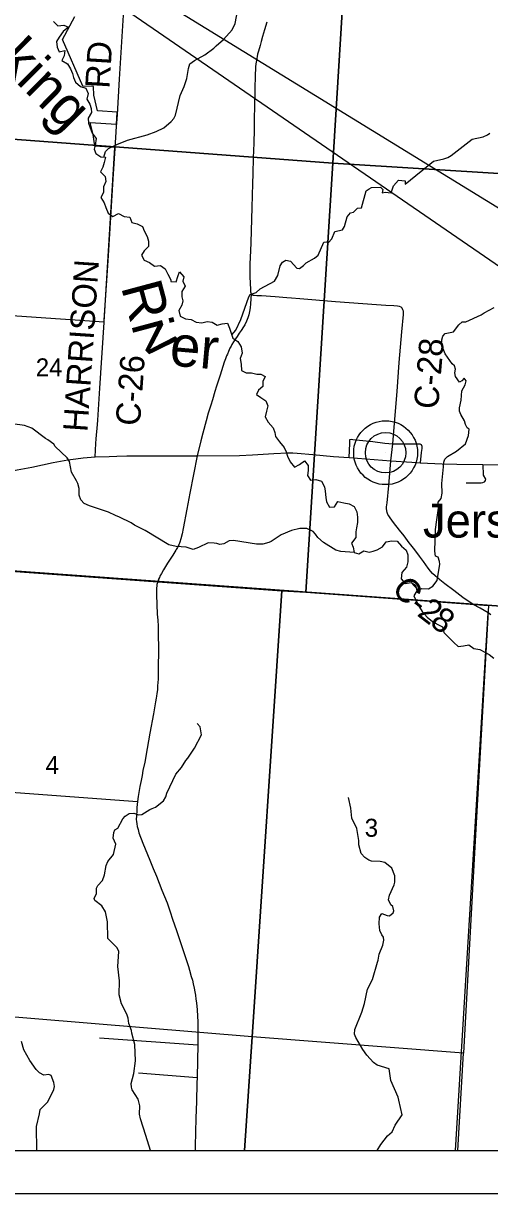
# Model space of a CAD drawing. Extents: x 0 to 91.3, y -0.7 to 22.
# Drawn here: x 6.125 to 7.212, y 14 to 16.725 of the extents above; entities that cross this region are included whole.
import ezdxf

# ---------------------------------------------------------------- set-up
doc = ezdxf.new("R2010")
doc.units = 0
for name, color, linetype in [('GM_X_City_Street', 7, 'Continuous'), ('GM_X_Corporation', 7, 'Continuous'), ('GM_X_County_Road', 7, 'Continuous'), ('GM_X_County_Road_Text', 7, 'Continuous'), ('GM_X_Major_River', 7, 'Continuous'), ('GM_X_Major_River_Text', 7, 'Continuous'), ('GM_X_Minor_River', 7, 'Continuous'), ('GM_X_Section_Text', 7, 'Continuous'), ('GM_X_Township_Road', 7, 'Continuous'), ('GM_X_Unincorporated', 7, 'Continuous'), ('GM_X_Unincorporated_Location', 7, 'Continuous'), ('GM_X_Unincorporated_Text', 7, 'Continuous'), ('SH_Data', 7, 'Continuous'), ('SH_Text', 7, 'Continuous')]:
    doc.layers.add(name, color=color, linetype=linetype)

msp = doc.modelspace()

# ---------------------------------------------------------------- linework, layer by layer
at = {"layer": 'GM_X_City_Street'}
for p, q in [((7.1321, 14.1), (7.2079, 15.352)), ((5.6815, 14.9665), (6.3908, 14.9126)), ((6.3026, 14.3628), (6.5313, 14.3463)), ((6.3934, 14.2814), (6.5298, 14.2704))]:
    msp.add_line(p, q, dxfattribs=at)
at = {"layer": 'GM_X_Corporation'}
for points in [[(4.8242, 18.6326), (4.7833, 18.1361), (4.7799, 18.0944), (4.7688, 17.9561), (4.7562, 17.8002), (4.7391, 17.5254), (4.7381, 17.5094), (4.7369, 17.4842), (4.7039, 16.921), (4.6966, 16.7952), (4.624, 15.5538), (4.6241, 15.5494), (4.6027, 15.2253), (4.5901, 15.0403), (4.5616, 14.5843), (4.5361, 14.2234), (4.5273, 14.1), (8.9, 14.1), (8.9, 20.9)], [(4.8242, 18.6326), (4.7833, 18.1361), (4.7799, 18.0944), (4.7688, 17.9561), (4.7562, 17.8002), (4.7391, 17.5254), (4.7381, 17.5094), (4.7369, 17.4842), (4.7039, 16.921), (4.6966, 16.7952), (4.624, 15.5538), (4.6241, 15.5494), (5.2553, 15.5081), (5.7371, 15.476), (6.438, 15.425), (7.1732, 15.3725), (7.6407, 15.3389), (8.8181, 15.2648), (8.9, 15.2596), (8.9, 20.4953)], [(5.8036, 16.0651), (6.313, 16.0296), (6.3385, 16.4356), (6.2918, 16.4387), (6.2873, 16.4662), (6.2807, 16.4943), (6.3421, 16.49), (6.3438, 16.5179), (6.2974, 16.521), (6.2893, 16.5576), (6.2884, 16.5776), (6.2639, 16.5784), (6.2162, 16.6875), (6.2451, 16.7407)]]:
    msp.add_lwpolyline(points, dxfattribs=at)
for points in [[(5.8879, 17.4801), (6.9092, 17.4181), (6.8465, 16.3992), (5.8298, 16.4755)], [(6.9092, 17.4181), (7.9172, 17.3589), (7.8571, 16.3365), (6.8465, 16.3992)], [(5.8298, 16.4755), (6.8465, 16.3992), (6.7835, 15.4003), (6.727, 15.4038), (5.7634, 15.4732)], [(6.8465, 16.3992), (7.8571, 16.3365), (7.7907, 15.3289), (7.2092, 15.3695), (6.7835, 15.4003)], [(4.5273, 14.1), (8.9, 14.1), (8.9, 15.2596), (8.8181, 15.2648), (7.6407, 15.3389), (7.1732, 15.3725), (6.438, 15.425), (5.7371, 15.476), (5.2553, 15.5081), (4.6241, 15.5494), (4.6027, 15.2253), (4.5901, 15.0403), (4.5616, 14.5843), (4.5361, 14.2234)], [(4.5286, 14.1), (8.9, 14.1), (8.9, 15.2593), (7.6407, 15.3389), (7.1732, 15.3725), (5.7332, 15.4763), (5.3098, 15.5058), (4.9415, 15.5315), (4.9055, 15.5345), (4.624, 15.5538)], [(5.7168, 15.4767), (5.7634, 15.4732), (6.727, 15.4038), (6.6586, 14.3652), (5.6446, 14.4487)], [(6.727, 15.4038), (6.7835, 15.4003), (7.2092, 15.3695), (7.1789, 14.8356), (7.1508, 14.3266), (6.6586, 14.3652)], [(5.6181, 14.1), (6.6403, 14.1), (6.6586, 14.3652), (5.6446, 14.4487)], [(6.6403, 14.1), (7.1375, 14.1), (7.1508, 14.3266), (6.6586, 14.3652)]]:
    msp.add_lwpolyline(points, close=True, dxfattribs=at)
at = {"layer": 'GM_X_County_Road'}
msp.add_line((6.3428, 16.4928), (6.3441, 16.5128), dxfattribs=at)
for points in [[(6.3441, 16.5128), (6.3491, 16.5947), (6.3656, 16.8567), (6.3814, 17.0978), (6.3885, 17.2334), (6.4013, 17.4498)], [(6.6924, 16.7276), (6.6872, 16.7094), (6.6824, 16.6941), (6.6792, 16.6827), (6.6765, 16.6735), (6.6727, 16.6603), (6.6707, 16.6529), (6.6698, 16.648), (6.6688, 16.6431), (6.6681, 16.6385), (6.6673, 16.6343), (6.6668, 16.6304), (6.6662, 16.6235), (6.6657, 16.6159), (6.6654, 16.6091), (6.6646, 16.5672), (6.6639, 16.531), (6.6632, 16.5031), (6.6626, 16.4778), (6.6625, 16.4456), (6.6609, 16.4117), (6.6597, 16.3745), (6.6589, 16.3516), (6.6575, 16.2961), (6.6553, 16.2148), (6.6542, 16.195), (6.6529, 16.1648), (6.6528, 16.1528), (6.653, 16.1416), (6.653, 16.1372), (6.6531, 16.1314), (6.6537, 16.1233), (6.6538, 16.1172), (6.6541, 16.1072), (6.6546, 16.0996), (6.6558, 16.0949), (6.6551, 16.0836), (6.6546, 16.0717), (6.6538, 16.0628), (6.6524, 16.054), (6.6506, 16.0464), (6.6482, 16.039), (6.6451, 16.0315), (6.6411, 16.0232), (6.6382, 16.0185), (6.6323, 16.0095), (6.6282, 16.0033), (6.6231, 15.996), (6.6194, 15.9904), (6.6146, 15.9833), (6.611, 15.9768), (6.609, 15.9734), (6.6064, 15.9685), (6.6028, 15.9606), (6.6004, 15.9549), (6.5986, 15.9509), (6.5959, 15.9436), (6.5931, 15.9359), (6.5896, 15.9256), (6.5833, 15.9056), (6.5796, 15.8937), (6.5751, 15.88), (6.5714, 15.8679), (6.5655, 15.8485), (6.5616, 15.8356), (6.5559, 15.817), (6.5512, 15.7995), (6.5434, 15.7709), (6.5387, 15.7527), (6.5301, 15.718)], [(6.339, 16.4332), (6.3424, 16.4858), (6.3428, 16.4928)], [(6.3136, 16.034), (6.3236, 16.184), (6.3345, 16.3626), (6.339, 16.4332)], [(6.9813, 15.7065), (6.9858, 15.7459), (6.99, 15.7942), (6.996, 15.868), (7.0012, 15.9355), (7.0071, 16.0065), (7.0111, 16.0467), (7.0108, 16.0543), (7.0097, 16.0579), (7.0078, 16.0616), (7.0053, 16.0639), (7.0018, 16.0653), (6.997, 16.066), (6.9881, 16.0668), (6.9701, 16.0678), (6.948, 16.0694), (6.8528, 16.0764), (6.7694, 16.0831), (6.7496, 16.0848), (6.7392, 16.0859), (6.7115, 16.088), (6.6798, 16.0901), (6.6689, 16.0907), (6.6631, 16.0912), (6.6608, 16.0915), (6.6583, 16.0926), (6.6558, 16.0949)], [(6.2926, 15.7156), (6.2937, 15.7468), (6.2945, 15.7577), (6.2975, 15.7905), (6.2984, 15.8006), (6.3036, 15.8756), (6.3132, 16.028), (6.3136, 16.034)], [(6.5301, 15.718), (6.6286, 15.7188), (6.6594, 15.7203), (6.7086, 15.7233), (6.7409, 15.7246), (6.7529, 15.7247), (6.7629, 15.724), (6.7998, 15.721), (6.8477, 15.7166), (6.8843, 15.7136), (6.9813, 15.7065), (7.0305, 15.703), (7.0496, 15.7018), (7.1008, 15.6994), (7.1352, 15.6986), (7.1957, 15.6977), (7.2485, 15.6967)], [(5.9032, 15.6474), (6.0541, 15.6743), (6.1102, 15.6849), (6.1444, 15.6918), (6.1946, 15.7021), (6.2285, 15.7083), (6.2474, 15.7112), (6.2642, 15.7133), (6.2926, 15.7156)], [(6.2926, 15.7156), (6.3247, 15.7165), (6.3427, 15.7168), (6.3664, 15.7175), (6.4076, 15.7179), (6.5301, 15.718)], [(6.5301, 15.718), (6.5133, 15.6312), (6.5106, 15.6184), (6.506, 15.5935), (6.4978, 15.549), (6.4951, 15.5362), (6.492, 15.5248), (6.4894, 15.5165), (6.487, 15.5107), (6.4859, 15.508), (6.4842, 15.5047), (6.4825, 15.5019), (6.4815, 15.4998), (6.4804, 15.4982), (6.473, 15.4866), (6.4613, 15.4679), (6.4559, 15.4599), (6.4513, 15.4522), (6.4466, 15.4438), (6.443, 15.4373), (6.4419, 15.4349), (6.4403, 15.4308), (6.44, 15.4299)], [(7.1734, 15.3719), (7.1492, 15.3882), (7.1285, 15.4039), (7.1073, 15.4199), (7.0957, 15.4293), (7.0845, 15.4383), (7.0783, 15.4441), (7.0739, 15.449), (7.0685, 15.4561), (7.0573, 15.4719), (7.0484, 15.4839), (7.0375, 15.4991), (7.0282, 15.5107), (7.0245, 15.5155), (7.0124, 15.5314), (7.0019, 15.5451), (6.988, 15.5627), (6.98, 15.5735), (6.9766, 15.5779), (6.9747, 15.5816), (6.9731, 15.5862), (6.9721, 15.59), (6.9716, 15.5955), (6.9717, 15.5993), (6.9727, 15.6083), (6.9771, 15.649), (6.9813, 15.7065)], [(6.44, 15.4299), (6.4382, 15.4245), (6.4364, 15.4179), (6.4357, 15.4144), (6.4354, 15.4103), (6.4351, 15.4036), (6.435, 15.3938), (6.4371, 15.3488), (6.4383, 15.335), (6.4389, 15.3214), (6.439, 15.3034), (6.4396, 15.2681), (6.4392, 15.2214), (6.439, 15.1981), (6.4379, 15.1821), (6.4373, 15.1733), (6.4362, 15.1648), (6.4352, 15.1583), (6.4343, 15.1533), (6.4331, 15.1452), (6.4321, 15.1404), (6.4284, 15.1173), (6.4199, 15.0718), (6.4139, 15.0367), (6.4078, 15.0045), (6.4037, 14.9853), (6.4016, 14.9736), (6.3992, 14.9618), (6.3965, 14.9476), (6.394, 14.934), (6.3924, 14.9243), (6.3908, 14.9126), (6.3895, 14.8991), (6.3891, 14.8922), (6.3885, 14.8794), (6.3882, 14.8708), (6.3886, 14.8663), (6.3893, 14.8606), (6.3906, 14.855), (6.3923, 14.8476), (6.3945, 14.8404), (6.4037, 14.816), (6.4201, 14.7763), (6.4278, 14.7568), (6.435, 14.7391), (6.4477, 14.7067), (6.4598, 14.6774), (6.4673, 14.6557), (6.4728, 14.6393), (6.4819, 14.6128), (6.49, 14.5894), (6.4952, 14.573), (6.5006, 14.5568), (6.5096, 14.5286), (6.5122, 14.52), (6.5163, 14.5054), (6.5189, 14.4966), (6.5211, 14.4881), (6.5232, 14.4782), (6.5249, 14.4699), (6.5263, 14.4622), (6.5273, 14.4531), (6.5283, 14.444), (6.53, 14.4279), (6.5315, 14.3994), (6.5315, 14.3808), (6.5317, 14.3532), (6.5313, 14.3463), (6.531, 14.3098), (6.5298, 14.2704), (6.5296, 14.257), (6.5282, 14.2144), (6.527, 14.1757), (6.5256, 14.1108), (6.5254, 14.1)], [(7.2144, 15.3476), (7.2079, 15.352), (7.1896, 15.3628), (7.1734, 15.3719)]]:
    msp.add_lwpolyline(points, dxfattribs=at)
at = {"layer": 'GM_X_Major_River'}
for points in [[(6.1956, 16.7293), (6.2055, 16.7194), (6.2191, 16.7205), (6.2301, 16.7159), (6.2179, 16.7061), (6.2088, 16.6928), (6.2019, 16.6826), (6.2034, 16.669), (6.2086, 16.6587), (6.2215, 16.6617), (6.2204, 16.6492), (6.215, 16.6382), (6.2275, 16.6302), (6.235, 16.6188), (6.2392, 16.6082), (6.2422, 16.5987), (6.2467, 16.5877), (6.2584, 16.5778), (6.2705, 16.5743), (6.2761, 16.5614), (6.2731, 16.5481), (6.2798, 16.5363), (6.2832, 16.5268), (6.2836, 16.5174), (6.2759, 16.5041), (6.277, 16.4924), (6.2808, 16.4814), (6.2856, 16.4692), (6.2947, 16.4566), (6.292, 16.4415), (6.2901, 16.4316), (6.2938, 16.4221), (6.3059, 16.4141), (6.3165, 16.413), (6.3134, 16.4008), (6.3104, 16.3898), (6.305, 16.3793), (6.316, 16.3686), (6.3171, 16.3568), (6.3117, 16.344), (6.3117, 16.3307), (6.3052, 16.3193), (6.3131, 16.3068), (6.3172, 16.2958), (6.3225, 16.2825), (6.3334, 16.2752), (6.3467, 16.2824)], [(6.3467, 16.2824), (6.36, 16.2751), (6.3729, 16.2736), (6.3781, 16.2614), (6.3902, 16.2583), (6.4023, 16.2515), (6.4065, 16.242), (6.4132, 16.2287), (6.4166, 16.218), (6.4166, 16.2055), (6.4063, 16.1953), (6.4002, 16.1851), (6.4066, 16.1737), (6.4187, 16.168), (6.4308, 16.1592), (6.4448, 16.1611), (6.4554, 16.1534), (6.4618, 16.1409), (6.469, 16.128)], [(6.469, 16.128), (6.4686, 16.1238), (6.4811, 16.123), (6.4853, 16.1355), (6.4891, 16.1465), (6.4993, 16.1347), (6.4963, 16.1244), (6.5023, 16.1127), (6.4943, 16.1002), (6.4942, 16.0881), (6.4965, 16.0786), (6.4945, 16.0683), (6.4873, 16.0559), (6.4903, 16.0429), (6.5031, 16.0365), (6.516, 16.0356), (6.5274, 16.0288), (6.5406, 16.0276), (6.5531, 16.0306), (6.5653, 16.029), (6.5766, 16.0218), (6.5884, 16.0255), (6.6005, 16.0266), (6.6058, 16.0152), (6.6095, 16.0038), (6.6133, 15.9917), (6.625, 15.9837), (6.6325, 15.9719), (6.6348, 15.9571), (6.6302, 15.9442), (6.6324, 15.9309), (6.6335, 15.9169), (6.6441, 15.9108), (6.6569, 15.9111), (6.6691, 15.908), (6.6785, 15.9076), (6.6884, 15.9026), (6.683, 15.8909), (6.6834, 15.8791), (6.6731, 15.8708), (6.6681, 15.8603), (6.6787, 15.8534), (6.6901, 15.8461), (6.6946, 15.8344), (6.6919, 15.8222), (6.6888, 15.8086), (6.6952, 15.7961), (6.7069, 15.7831), (6.711, 15.7721), (6.7129, 15.7626), (6.7219, 15.7505), (6.7332, 15.7375), (6.7374, 15.7273), (6.7404, 15.717), (6.7471, 15.7041), (6.757, 15.6912), (6.7684, 15.698), (6.7801, 15.7063), (6.7888, 15.6956), (6.7888, 15.6835), (6.7872, 15.6717), (6.7944, 15.6615), (6.8065, 15.6629), (6.8198, 15.6587), (6.8265, 15.6454), (6.828, 15.6352), (6.8302, 15.6211), (6.8313, 15.6105), (6.8381, 15.5984), (6.8499, 15.5994), (6.8579, 15.6115), (6.8715, 15.6085), (6.8844, 15.6058), (6.8961, 15.5996), (6.9021, 15.5875), (6.904, 15.575), (6.9036, 15.5628), (6.9012, 15.5503), (6.8997, 15.5409), (6.8996, 15.528), (6.8901, 15.5147), (6.8939, 15.5052), (6.8961, 15.4927), (6.9071, 15.4893), (6.9185, 15.4968), (6.9306, 15.4933), (6.9401, 15.4956), (6.9496, 15.499), (6.9617, 15.5057), (6.9709, 15.5178), (6.9834, 15.5201), (6.9963, 15.5193), (7.0061, 15.5078), (7.017, 15.4979), (7.0212, 15.4873), (7.0211, 15.4714), (7.0177, 15.4589), (7.0074, 15.4464), (7.0058, 15.4313), (7.0152, 15.4206), (7.0289, 15.4228)], [(7.0289, 15.4228), (7.0387, 15.4167), (7.0421, 15.4038), (7.0352, 15.3921), (7.0416, 15.3788), (7.048, 15.3651), (7.0548, 15.3556), (7.0661, 15.3423), (7.0786, 15.3324), (7.0907, 15.3251), (7.102, 15.3194), (7.105, 15.3065), (7.1175, 15.2943), (7.1281, 15.2833), (7.1383, 15.2738), (7.1508, 15.2753), (7.1629, 15.2775), (7.175, 15.2691), (7.1887, 15.2668), (7.2008, 15.261), (7.2106, 15.2553), (7.2212, 15.2469)]]:
    msp.add_lwpolyline(points, dxfattribs=at)
at = {"layer": 'GM_X_Minor_River'}
for points in [[(6.3122, 16.4134), (6.3165, 16.4266), (6.3237, 16.4338), (6.3431, 16.4431), (6.3674, 16.4525), (6.4134, 16.4655), (6.4346, 16.4729), (6.4525, 16.4819), (6.4696, 16.4962), (6.4754, 16.5034), (6.4792, 16.5113), (6.4908, 16.5568), (6.4997, 16.578), (6.5062, 16.5965), (6.5098, 16.6196), (6.5132, 16.6302), (6.5239, 16.6385), (6.5478, 16.6513), (6.5688, 16.6674), (6.5745, 16.6727), (6.5916, 16.687), (6.6115, 16.7096), (6.6188, 16.7244), (6.625, 16.7574)], [(6.6108, 15.9996), (6.6201, 16.0103), (6.632, 16.0349), (6.6505, 16.0882), (6.6539, 16.0932), (6.6672, 16.0984), (6.6771, 16.1063), (6.7106, 16.1247), (6.7182, 16.1375), (6.7237, 16.1599), (6.7286, 16.1689), (6.737, 16.1738), (6.7472, 16.1711), (6.7623, 16.1547), (6.7687, 16.1539), (6.7775, 16.1611), (6.784, 16.1671), (6.8038, 16.1784), (6.8117, 16.1847), (6.8256, 16.2154), (6.8309, 16.2161), (6.8358, 16.2142), (6.8442, 16.2229), (6.8511, 16.2399), (6.8686, 16.2443), (6.8732, 16.2515), (6.8797, 16.2742), (6.8877, 16.284), (6.8942, 16.2855), (6.9034, 16.2946), (6.9132, 16.2953), (6.924, 16.335), (6.9309, 16.3399), (6.9362, 16.3425), (6.9571, 16.3432), (6.9624, 16.3378), (6.9616, 16.3302), (6.968, 16.3321), (6.982, 16.3301), (6.9878, 16.3464), (6.9996, 16.36), (7.0148, 16.358), (7.0151, 16.3504), (7.0806, 16.4039), (7.1053, 16.4094), (7.114, 16.4128), (7.1224, 16.4169), (7.1708, 16.4549), (7.1966, 16.4608), (7.2068, 16.4649), (7.2122, 16.4691)], [(7.0289, 15.4228), (7.0451, 15.4052), (7.0534, 15.4086), (7.069, 15.4085), (7.0796, 15.4141), (7.0896, 15.4277), (7.0955, 15.4656), (7.0951, 15.4721), (7.0914, 15.4816), (7.0857, 15.4843), (7.0839, 15.496), (7.0853, 15.5464), (7.0888, 15.5688), (7.0928, 15.5957), (7.0921, 15.6101), (7.099, 15.6188), (7.1009, 15.6309), (7.1003, 15.6537), (7.1039, 15.6923), (7.1051, 15.7033), (7.1071, 15.7097), (7.1132, 15.7165), (7.1348, 15.7289), (7.1554, 15.7455), (7.1623, 15.7655), (7.1643, 15.7803), (7.1594, 15.7834), (7.1557, 15.7906), (7.1534, 15.799), (7.1448, 15.8138), (7.1418, 15.8218), (7.1411, 15.8294), (7.1457, 15.8472), (7.1466, 15.8695), (7.155, 15.8831), (7.1566, 15.8926), (7.1521, 15.8983), (7.1471, 15.8923), (7.1411, 15.8897), (7.1324, 15.9022), (7.1309, 15.9113), (7.1325, 15.92), (7.1299, 15.9276), (7.1242, 15.9322), (7.1081, 15.9555), (7.0998, 15.9764), (7.1003, 15.9877), (7.1026, 15.9968), (7.1079, 16.0025), (7.1277, 16.0065), (7.1399, 16.0228), (7.1475, 16.0299), (7.1559, 16.0299), (7.192, 16.0463), (7.1988, 16.0509), (7.2224, 16.0636)], [(6.8961, 15.4927), (6.8651, 15.4947), (6.853, 15.4982), (6.8243, 15.5158), (6.8111, 15.5276), (6.8055, 15.5356), (6.8002, 15.5417), (6.7858, 15.5486), (6.7695, 15.5487), (6.7498, 15.5439), (6.7255, 15.5342), (6.7026, 15.518), (6.6969, 15.5158), (6.6829, 15.5121), (6.6681, 15.5125), (6.6151, 15.5204), (6.6048, 15.5197), (6.5923, 15.5133), (6.5832, 15.5115), (6.576, 15.5134), (6.5699, 15.5146), (6.5555, 15.5155), (6.5331, 15.5042), (6.5205, 15.5001), (6.5043, 15.5055), (6.4808, 15.5068), (6.4641, 15.5107), (6.4086, 15.5436), (6.384, 15.5563), (6.3761, 15.562), (6.3488, 15.5751), (6.3401, 15.5789), (6.3231, 15.5866), (6.2792, 15.6013), (6.2664, 15.607), (6.2592, 15.6151), (6.2551, 15.6261), (6.2548, 15.642), (6.2522, 15.6534), (6.2492, 15.6595), (6.2372, 15.6796), (6.2324, 15.7043), (6.2272, 15.7131), (6.1989, 15.7398), (6.1959, 15.7451), (6.1819, 15.7554), (6.1766, 15.7585), (6.1445, 15.7822), (6.1279, 15.7884), (6.0998, 15.7923)], [(6.4216, 14.1), (6.4105, 14.1355), (6.3982, 14.1739), (6.396, 14.1849), (6.3961, 14.2046), (6.3928, 14.2201), (6.3789, 14.2418), (6.3767, 14.2479), (6.3763, 14.2563), (6.3825, 14.2797), (6.3861, 14.3093), (6.3848, 14.3468), (6.3781, 14.3734), (6.3774, 14.3795), (6.371, 14.3958), (6.3692, 14.4083), (6.3659, 14.4178), (6.3535, 14.4422), (6.3479, 14.463), (6.3492, 14.4953), (6.3453, 14.5287), (6.3477, 14.5639), (6.344, 14.5726), (6.3221, 14.594), (6.3212, 14.6327), (6.3168, 14.6562), (6.3081, 14.6703), (6.2919, 14.6825), (6.2897, 14.6875), (6.2954, 14.6988), (6.2955, 14.7113), (6.2982, 14.717), (6.3092, 14.7294), (6.3142, 14.7423), (6.3178, 14.7639), (6.322, 14.7733), (6.3353, 14.7892), (6.3408, 14.8134), (6.3344, 14.8279), (6.3356, 14.8407), (6.3379, 14.8468), (6.3448, 14.8505), (6.357, 14.8728), (6.362, 14.8785), (6.3715, 14.8849), (6.3825, 14.8856), (6.3935, 14.8821), (6.4011, 14.8828), (6.4197, 14.8945), (6.425, 14.8963), (6.433, 14.9001), (6.4513, 14.9147), (6.457, 14.9242), (6.459, 14.9325), (6.4801, 14.9764), (6.4938, 14.9918), (6.5038, 15.0085), (6.508, 15.0137), (6.5236, 15.0375), (6.5401, 15.0681), (6.5368, 15.0867), (6.53, 15.0944)], [(6.9676, 14.7706), (6.9562, 14.7734), (6.9365, 14.7742), (6.9301, 14.7762), (6.9206, 14.7823), (6.9124, 14.7918), (6.9072, 14.8123), (6.9065, 14.8222), (6.9025, 14.8503), (6.8908, 14.8742), (6.8879, 14.8977), (6.8824, 14.922)], [(6.9499, 14.1), (6.9582, 14.1144), (6.9739, 14.1348), (6.9842, 14.1435), (6.9918, 14.1597), (7.0079, 14.1835), (7.0001, 14.2173), (6.9983, 14.2249), (6.9814, 14.2637), (6.9774, 14.2906), (6.9494, 14.2991), (6.9411, 14.3056), (6.9256, 14.3224), (6.9162, 14.3353), (6.9001, 14.3635), (6.8971, 14.3711), (6.8975, 14.3817), (6.9137, 14.4222), (6.9203, 14.4426), (6.9269, 14.4759), (6.9388, 14.4986), (6.9504, 14.5387), (6.9519, 14.5436), (6.9539, 14.5573), (6.9631, 14.5788), (6.9654, 14.5898), (6.964, 14.597), (6.9602, 14.6023), (6.9561, 14.6126), (6.9539, 14.6285), (6.9547, 14.6437), (6.9601, 14.6524), (6.973, 14.6474), (6.9783, 14.647), (6.9866, 14.6534), (6.9882, 14.6587), (6.986, 14.6685), (6.9811, 14.6727), (6.9758, 14.6841), (6.9782, 14.6951), (6.9893, 14.7186), (6.9905, 14.7254), (6.9905, 14.7337), (6.9905, 14.7402), (6.9838, 14.758), (6.9676, 14.7706)], [(6.1566, 14.1), (6.1559, 14.156), (6.1629, 14.1855), (6.1641, 14.1957), (6.182, 14.2138), (6.1962, 14.2422), (6.1973, 14.2497), (6.1963, 14.2585), (6.1899, 14.2748), (6.1846, 14.2771), (6.1725, 14.276), (6.1626, 14.2814), (6.1547, 14.289), (6.1397, 14.3096), (6.1258, 14.3351), (6.121, 14.3545)]]:
    msp.add_lwpolyline(points, dxfattribs=at)
at = {"layer": 'GM_X_Township_Road'}
for points in [[(6.8843, 15.7136), (6.8856, 15.7464), (6.8855, 15.7526), (6.8861, 15.756), (6.8891, 15.7563), (6.8925, 15.756), (6.9396, 15.751), (6.9674, 15.7475), (6.9858, 15.7459), (6.9953, 15.7459), (7.0035, 15.7459), (7.0375, 15.7456), (7.049, 15.7454), (7.0524, 15.7442), (7.0539, 15.7403), (7.0539, 15.7352), (7.0523, 15.7255), (7.0496, 15.7018)], [(7.1957, 15.6977), (7.1964, 15.6729), (7.2017, 15.6636), (7.201, 15.6605), (7.1999, 15.6581), (7.1989, 15.6568), (7.1968, 15.6557), (7.1947, 15.6549), (7.1918, 15.6544), (7.18, 15.6539), (7.17, 15.6542), (7.1566, 15.6539)]]:
    msp.add_lwpolyline(points, dxfattribs=at)
at = {"layer": 'GM_X_Unincorporated'}
for radius in [0.0744, 0.0472]:
    msp.add_circle((6.9692, 15.7251), radius, dxfattribs=at)
at = {"layer": 'GM_X_Unincorporated_Location'}
msp.add_line((6.9692, 15.7251), (6.9692, 15.7251), dxfattribs=at)
at = {"layer": 'SH_Data'}
for p, q in [((2.1, 14.1), (8.9, 14.1)), ((2, 14), (9, 14))]:
    msp.add_line(p, q, dxfattribs=at)
at = {"layer": 'SH_Text'}
msp.add_lwpolyline([(9.2012, 14.8079), (5.3743, 17.4358), (9.2012, 15.0876)], close=True, dxfattribs=at)

# ---------------------------------------------------------------- texts
at = {"layer": 'GM_X_County_Road_Text'}
for s, height, rotation, p in [('RD', 0.05682, 86.5523, (6.3257, 16.5721)), ('HARRISON', 0.05682, 86.1242, (6.2741, 15.7725)), ('C-28', 0.05682, 85.2082, (7.0914, 15.8253)), ('C-26', 0.05682, 85.8892, (6.3965, 15.7864)), ('C', 0.0568, 308.3227, (6.9819, 15.4089)), ('-', 0.0568, 322.4898, (7.0218, 15.3615)), ('2', 0.0568, 322.4244, (7.0403, 15.3473)), ('8', 0.0568, 324.1266, (7.0695, 15.3249))]:
    msp.add_text(s, height=height, rotation=rotation, dxfattribs=at).set_placement(p)
at = {"layer": 'GM_X_Major_River_Text'}
for s, height, rotation, p in [('Licking', 0.09471, 314.9945, (5.9464, 16.7478)), ('Ri', 0.09471, 284.9978, (6.3521, 16.1117)), ('v', 0.0947, 314.9956, (6.3915, 15.9811)), ('er', 0.0947, 355.0011, (6.4639, 15.9286))]:
    msp.add_text(s, height=height, rotation=rotation, dxfattribs=at).set_placement(p)
at = {"layer": 'GM_X_Section_Text'}
for s, height, p in [('24', 0.04186, (6.1539, 15.9029)), ('4', 0.0419, (6.1768, 14.9771)), ('3', 0.0419, (6.9206, 14.8309))]:
    msp.add_text(s, height=height, rotation=0, dxfattribs=at).set_placement(p)
at = {"layer": 'GM_X_Unincorporated_Text'}
msp.add_text('Jersey', height=0.07898, rotation=0, dxfattribs=at).set_placement((7.0564, 15.5275))

doc.saveas('drawing.dxf')
